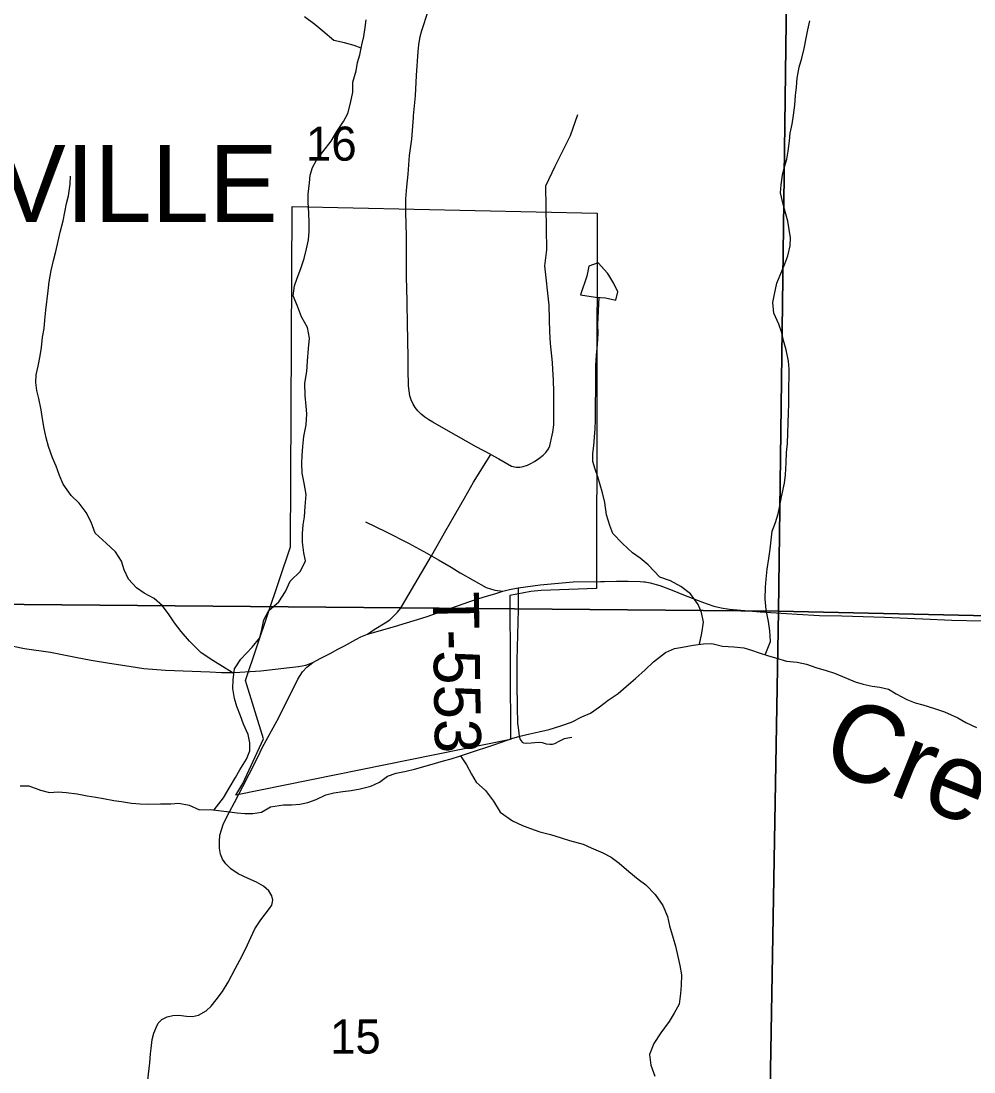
# Model space of a CAD drawing. Extents: x 0 to 34, y 0 to 22.
# Drawn here: x 24.083 to 25.254, y 17.051 to 18.342 of the extents above; entities that cross this region are included whole.
import ezdxf

# ---------------------------------------------------------------- set-up
doc = ezdxf.new("R2010")
doc.units = 0
for name, color, linetype in [('GM_X_City_Street', 7, 'Continuous'), ('GM_X_Corporation', 7, 'Continuous'), ('GM_X_Corporation_Text', 7, 'Continuous'), ('GM_X_Minor_Lake', 7, 'Continuous'), ('GM_X_Minor_River', 7, 'Continuous'), ('GM_X_Minor_River_Text', 7, 'Continuous'), ('GM_X_Section_Text', 7, 'Continuous'), ('GM_X_State_Route', 7, 'Continuous'), ('GM_X_Township_Road', 7, 'Continuous'), ('GM_X_Township_Road_Text', 7, 'Continuous')]:
    doc.layers.add(name, color=color, linetype=linetype)

msp = doc.modelspace()

# ---------------------------------------------------------------- linework, layer by layer
at = {"layer": 'GM_X_City_Street'}
for points in [[(24.5061, 17.7266), (24.5315, 17.7141), (24.559, 17.7002), (24.5815, 17.6882), (24.5875, 17.6847), (24.5961, 17.6798)], [(24.5961, 17.6798), (24.6116, 17.671), (24.6226, 17.6641), (24.6545, 17.646), (24.6651, 17.6427), (24.6751, 17.6415)]]:
    msp.add_lwpolyline(points, dxfattribs=at)
at = {"layer": 'GM_X_Corporation'}
for points in [[(24.0091, 18.6407), (25.0268, 18.6245), (25.0136, 17.617), (23.994, 17.626)], [(25.0268, 18.6245), (26.0385, 18.6067), (26.0272, 17.5944), (25.0136, 17.617)], [(24.3471, 17.3906), (24.3555, 17.4051), (24.3811, 17.4601), (24.3588, 17.5318), (24.4142, 17.696), (24.416, 18.114), (24.7909, 18.106), (24.7901, 17.6448), (24.7223, 17.6424), (24.7096, 17.641), (24.6835, 17.6361), (24.6843, 17.4591)], [(25.0136, 17.617), (24.9957, 16.5834), (23.9803, 16.5962), (23.994, 17.626)], [(26.0272, 17.5944), (26.0142, 16.5672), (24.9957, 16.5834), (25.0136, 17.617)]]:
    msp.add_lwpolyline(points, close=True, dxfattribs=at)
at = {"layer": 'GM_X_Minor_Lake'}
for points in [[(24.8051, 18.0295), (24.8035, 18.032), (24.7921, 18.0449), (24.7807, 18.0407), (24.7781, 18.0285), (24.7704, 18.0054)], [(24.7704, 18.0054), (24.7888, 18.0028), (24.8013, 18.002), (24.8138, 17.999), (24.8165, 18.0093), (24.8115, 18.0195), (24.8051, 18.0295)]]:
    msp.add_lwpolyline(points, dxfattribs=at)
at = {"layer": 'GM_X_Minor_River'}
for points in [[(24.3202, 17.3727), (24.3318, 17.3874), (24.3386, 17.3992), (24.3465, 17.4125), (24.3518, 17.422), (24.3601, 17.435), (24.3643, 17.4452), (24.3643, 17.4551), (24.3623, 17.4653), (24.3566, 17.4778), (24.3528, 17.4881), (24.3482, 17.4998), (24.3452, 17.5097), (24.3432, 17.5218), (24.3436, 17.5325), (24.3455, 17.5458), (24.353, 17.5579), (24.367, 17.5724), (24.3765, 17.5842), (24.3791, 17.5941), (24.3814, 17.6062), (24.3874, 17.6176), (24.3999, 17.6283), (24.4082, 17.6409), (24.4139, 17.6538), (24.4264, 17.666), (24.4324, 17.6785), (24.4305, 17.6884), (24.429, 17.7017), (24.4289, 17.7123), (24.4297, 17.7229), (24.4312, 17.7328), (24.4323, 17.7454), (24.4334, 17.7602), (24.4311, 17.7742), (24.4284, 17.7863), (24.428, 17.7981), (24.4283, 17.808), (24.4291, 17.819), (24.4306, 17.8315), (24.4332, 17.8456), (24.4343, 17.8593), (24.4335, 17.8688), (24.432, 17.8817), (24.4319, 17.8968), (24.4342, 17.9113), (24.4349, 17.9238), (24.4364, 17.9394), (24.4375, 17.9523), (24.4352, 17.9652), (24.4276, 17.9785), (24.4226, 17.9914), (24.4173, 18.0043), (24.4191, 18.0164), (24.4225, 18.0259), (24.427, 18.0377), (24.4308, 18.0502), (24.4338, 18.062), (24.4361, 18.073), (24.4372, 18.0833), (24.4372, 18.0939), (24.4368, 18.1061), (24.436, 18.119), (24.4359, 18.1292), (24.4374, 18.1429), (24.4385, 18.1524), (24.4412, 18.1619), (24.4465, 18.1718), (24.454, 18.1813), (24.4642, 18.1943), (24.471, 18.2061), (24.4794, 18.2186), (24.4847, 18.2281), (24.4877, 18.241), (24.4907, 18.2543), (24.4906, 18.2669), (24.4948, 18.2809), (24.4966, 18.2908), (24.4993, 18.3003), (24.5019, 18.3125), (24.5042, 18.3227), (24.506, 18.3338), (24.5071, 18.3433)], [(24.501, 18.3085), (24.4924, 18.3117), (24.4803, 18.3151), (24.4674, 18.3181), (24.4537, 18.3294), (24.4442, 18.3377), (24.4312, 18.3472)], [(24.9972, 17.5633), (25.0038, 17.5797), (25.0033, 17.5926), (25.0014, 17.604), (24.9984, 17.6184), (24.9972, 17.6321), (24.9979, 17.6465), (24.9986, 17.656), (24.9998, 17.6686), (25.002, 17.6815), (25.0035, 17.6929), (25.0046, 17.7039), (25.0061, 17.7153), (25.0099, 17.7259), (25.0133, 17.7366), (25.0155, 17.7464), (25.0174, 17.7575), (25.0211, 17.7742), (25.0223, 17.7844), (25.023, 17.7989), (25.0237, 17.8118), (25.0248, 17.8228), (25.0252, 17.8357), (25.0255, 17.8478), (25.0259, 17.8604), (25.0266, 17.871), (25.0266, 17.8938), (25.0269, 17.9037), (25.0269, 17.9143), (25.0261, 17.9238), (25.023, 17.9378), (25.02, 17.9492), (25.0177, 17.9587), (25.0142, 17.9693), (25.0081, 17.9829), (25.0066, 17.9959), (25.0088, 18.0065), (25.0119, 18.0198), (25.0156, 18.0297), (25.0217, 18.0437), (25.0251, 18.0532), (25.0281, 18.0658), (25.0284, 18.0757), (25.0269, 18.0859), (25.0253, 18.0958), (25.0211, 18.1106), (25.0188, 18.1201), (25.0161, 18.1307), (25.0169, 18.1406), (25.0188, 18.1527), (25.021, 18.1626), (25.024, 18.1721), (25.0255, 18.182), (25.0274, 18.1945), (25.0281, 18.204), (25.0304, 18.215), (25.0322, 18.2264), (25.0337, 18.2386), (25.0348, 18.2504), (25.0359, 18.2606), (25.0367, 18.2716), (25.0393, 18.2853), (25.0423, 18.2963), (25.0453, 18.3081), (25.0479, 18.321), (25.0498, 18.3309), (25.0521, 18.3423)], [(24.3447, 17.5402), (24.3337, 17.5469), (24.3189, 17.5563), (24.3044, 17.5658), (24.29, 17.5798), (24.2797, 17.5919), (24.2717, 17.6025), (24.2649, 17.6123), (24.2569, 17.6233), (24.2466, 17.6324), (24.2344, 17.6388), (24.2249, 17.6456), (24.215, 17.6562), (24.2097, 17.6676), (24.2063, 17.6782), (24.199, 17.6899), (24.1876, 17.7005), (24.1743, 17.7126), (24.1693, 17.7263), (24.1629, 17.738), (24.1545, 17.7494), (24.1446, 17.7589), (24.1347, 17.7729), (24.1305, 17.7835), (24.1263, 17.7949), (24.1217, 17.8051), (24.1168, 17.8191), (24.1141, 17.8298), (24.1114, 17.8412), (24.1095, 17.8533), (24.1076, 17.8643), (24.1049, 17.8783), (24.1026, 17.8878), (24.1014, 17.8977), (24.1018, 17.9072), (24.104, 17.9178), (24.1066, 17.9304), (24.1081, 17.9406), (24.1096, 17.9535), (24.1115, 17.9642), (24.1122, 17.9744), (24.1137, 17.9866), (24.1163, 18.0105), (24.1178, 18.0215), (24.1201, 18.0352), (24.1231, 18.0477), (24.1257, 18.0588), (24.1287, 18.0713), (24.1313, 18.0823), (24.1347, 18.0964), (24.137, 18.107), (24.1388, 18.1177), (24.1415, 18.1272), (24.1433, 18.1416), (24.1437, 18.1511)], [(24.9168, 17.5761), (24.9195, 17.5897), (24.9214, 17.6034), (24.9191, 17.6152), (24.9149, 17.625), (24.9057, 17.6383), (24.8939, 17.647), (24.881, 17.6541), (24.8681, 17.6587), (24.8537, 17.6738), (24.8438, 17.6821), (24.8343, 17.6885), (24.8221, 17.6999), (24.8103, 17.7124), (24.8065, 17.7222), (24.8023, 17.7351), (24.8004, 17.7503), (24.7977, 17.7621), (24.7916, 17.7818), (24.7885, 17.7913), (24.7858, 17.8008), (24.7858, 17.8106), (24.7869, 17.8201), (24.7876, 17.8308), (24.7884, 17.841), (24.7887, 17.8513), (24.7891, 17.8638), (24.7891, 17.8737), (24.7894, 17.8862), (24.7893, 17.9185), (24.7901, 17.9314), (24.7912, 17.9443), (24.7923, 17.958), (24.7919, 17.969), (24.7936, 18.0025)], [(24.8168, 17.5157), (24.8267, 17.5241), (24.838, 17.534), (24.8501, 17.5447), (24.86, 17.5546), (24.8751, 17.566), (24.8861, 17.571), (24.896, 17.5726), (24.9089, 17.5749), (24.9214, 17.5768), (24.9317, 17.5772), (24.9449, 17.5739), (24.959, 17.5728), (24.9711, 17.5717), (24.9806, 17.569), (24.9901, 17.5656), (25.0004, 17.5623), (25.0102, 17.5593), (25.0235, 17.5555), (25.0368, 17.554), (25.0482, 17.5518), (25.0596, 17.5476), (25.0725, 17.5439), (25.0824, 17.5405), (25.0972, 17.5345), (25.1078, 17.53), (25.1177, 17.5273), (25.1287, 17.5247), (25.1382, 17.5236), (25.1488, 17.521), (25.1583, 17.5153), (25.1716, 17.5081), (25.1815, 17.504), (25.191, 17.5017), (25.2054, 17.4972), (25.2176, 17.4931), (25.2339, 17.4859), (25.2438, 17.4799), (25.2571, 17.4739)], [(24.082, 17.4022), (24.0927, 17.4022), (24.1071, 17.3969), (24.1181, 17.3939), (24.1287, 17.3947), (24.1386, 17.394), (24.1519, 17.3922), (24.1644, 17.3899), (24.175, 17.3881), (24.1845, 17.3866), (24.1971, 17.3843), (24.2066, 17.3828), (24.2187, 17.381), (24.2293, 17.3803), (24.2392, 17.3799), (24.2544, 17.38), (24.2673, 17.38), (24.2768, 17.3808), (24.2897, 17.3785), (24.3022, 17.3729), (24.3155, 17.3733), (24.3288, 17.3715), (24.339, 17.3704), (24.3485, 17.3689), (24.358, 17.3681), (24.3679, 17.3682), (24.3785, 17.3697), (24.3895, 17.3766), (24.4054, 17.3789), (24.4153, 17.3789), (24.4255, 17.3797), (24.4354, 17.3817), (24.4456, 17.3855), (24.4574, 17.3912), (24.4672, 17.3935), (24.4786, 17.3951), (24.4885, 17.3966), (24.4999, 17.3986), (24.5127, 17.402), (24.5234, 17.4066), (24.5332, 17.4139), (24.5438, 17.4177), (24.5563, 17.4204), (24.5666, 17.4227), (24.5795, 17.4262), (24.5924, 17.43), (24.6022, 17.4331), (24.6117, 17.4354), (24.6219, 17.4388), (24.6341, 17.4427), (24.6439, 17.4461), (24.6542, 17.4492), (24.664, 17.4526), (24.6735, 17.4557), (24.686, 17.4603), (24.6959, 17.4634), (24.7084, 17.4661), (24.7194, 17.4684), (24.7319, 17.4714), (24.7463, 17.476), (24.7596, 17.4806), (24.7721, 17.4868), (24.7827, 17.4913), (24.7937, 17.4994), (24.8043, 17.5074), (24.8168, 17.5157)], [(24.623, 17.4392), (24.6303, 17.4282), (24.6364, 17.4165), (24.6421, 17.4066), (24.6539, 17.3964), (24.6634, 17.3835), (24.6718, 17.3699), (24.687, 17.3593), (24.6992, 17.3533), (24.709, 17.3499), (24.7204, 17.3458), (24.7337, 17.3424), (24.7466, 17.3382), (24.7569, 17.3352), (24.7736, 17.3304), (24.7835, 17.3262), (24.7979, 17.3198), (24.8082, 17.3145), (24.818, 17.3073), (24.8298, 17.2968), (24.8412, 17.2877), (24.8507, 17.2805), (24.8622, 17.2688), (24.8717, 17.2551), (24.8774, 17.2415), (24.8797, 17.2301), (24.8843, 17.2149), (24.887, 17.2054), (24.89, 17.1926), (24.8927, 17.1816), (24.8946, 17.1702), (24.8943, 17.1569), (24.8932, 17.147), (24.8917, 17.1341), (24.8856, 17.1231), (24.8796, 17.1128), (24.869, 17.0987), (24.8607, 17.0858), (24.8554, 17.0721), (24.8569, 17.0592), (24.8619, 17.0456)]]:
    msp.add_lwpolyline(points, dxfattribs=at)
at = {"layer": 'GM_X_State_Route'}
for points in [[(24.5652, 18.2232), (24.5654, 18.2253), (24.5677, 18.2498), (24.5689, 18.275), (24.5711, 18.3043), (24.572, 18.3125), (24.5736, 18.3227), (24.5755, 18.3301), (24.5834, 18.354)], [(24.5558, 18.1236), (24.5571, 18.1381), (24.5589, 18.1538), (24.5605, 18.1767), (24.5631, 18.1969), (24.5652, 18.2232)], [(24.5088, 17.5884), (24.517, 17.5942), (24.5305, 17.6025), (24.5362, 17.6063), (24.5413, 17.6109), (24.5456, 17.6154), (24.5491, 17.6201), (24.5518, 17.624), (24.5752, 17.6638), (24.5875, 17.6847), (24.6049, 17.7158), (24.628, 17.7556), (24.6391, 17.7752), (24.6601, 17.8092), (24.6423, 17.8187), (24.6056, 17.8395), (24.5891, 17.849), (24.5842, 17.8517), (24.5794, 17.8552), (24.5749, 17.8588), (24.5708, 17.8629), (24.5672, 17.8672), (24.5647, 17.8712), (24.5623, 17.8765), (24.5607, 17.8813), (24.5592, 17.8938), (24.5588, 17.9139), (24.5588, 17.9286), (24.5581, 17.9707), (24.5575, 17.9946), (24.5569, 18.016), (24.5567, 18.0241), (24.5567, 18.0502), (24.5565, 18.0781), (24.5559, 18.1067), (24.5558, 18.1236)], [(24.5088, 17.5884), (24.5421, 17.598), (24.5809, 17.6099), (24.6344, 17.6287), (24.6457, 17.6322), (24.6551, 17.6352), (24.6653, 17.6382), (24.6751, 17.6415), (24.6833, 17.6433), (24.6939, 17.6456), (24.7208, 17.6493), (24.7613, 17.6529), (24.7951, 17.6531), (24.7999, 17.6532)], [(24.7999, 17.6532), (24.8145, 17.6536), (24.8291, 17.6537), (24.8438, 17.6533), (24.8482, 17.6529)], [(24.8482, 17.6529), (24.85, 17.6527), (24.8561, 17.6517), (24.8679, 17.6483), (24.8833, 17.6428), (24.8971, 17.637), (24.9202, 17.6277), (24.9343, 17.6228), (24.9434, 17.6209), (24.9536, 17.6194), (24.9912, 17.6162), (25.0368, 17.613), (25.0641, 17.6116), (25.0914, 17.6111), (25.1438, 17.6096), (25.1911, 17.6072), (25.2266, 17.6056), (25.263, 17.6051)], [(24.4414, 17.5536), (24.4516, 17.559), (24.4628, 17.5649), (24.4724, 17.5701), (24.4803, 17.5743), (24.4946, 17.5822), (24.5007, 17.5853), (24.5088, 17.5884)], [(24.0411, 17.5803), (24.0875, 17.5711), (24.1192, 17.5663), (24.1501, 17.5605), (24.1692, 17.5567), (24.1916, 17.5528), (24.2106, 17.5502), (24.2341, 17.5465), (24.2607, 17.5445), (24.3149, 17.5421), (24.3293, 17.5413), (24.344, 17.5414), (24.3519, 17.5418), (24.3647, 17.5427)], [(24.3768, 17.4435), (24.3799, 17.4497), (24.3972, 17.4817), (24.4157, 17.518), (24.4232, 17.5332), (24.429, 17.5421), (24.4344, 17.5479), (24.4414, 17.5536)], [(24.413, 17.5475), (24.4241, 17.5488), (24.4329, 17.5503), (24.4414, 17.5536)], [(24.3647, 17.5427), (24.3776, 17.5436), (24.413, 17.5475)], [(24.3453, 17.3818), (24.3554, 17.4015), (24.3711, 17.4318), (24.3768, 17.4435)], [(24.2378, 17.0302), (24.2412, 17.0618), (24.2423, 17.0731), (24.2428, 17.0797), (24.2443, 17.0906), (24.2461, 17.0983), (24.2493, 17.1063), (24.2515, 17.1105), (24.2559, 17.1151), (24.2625, 17.1183), (24.2695, 17.1199), (24.2771, 17.1206), (24.2863, 17.1193), (24.2936, 17.1188), (24.3013, 17.1204), (24.3106, 17.1256), (24.3166, 17.1317), (24.3227, 17.1392), (24.3304, 17.1497), (24.3377, 17.1612), (24.3463, 17.1773), (24.3549, 17.1935), (24.3615, 17.2069), (24.3654, 17.216), (24.3704, 17.2265), (24.3777, 17.2376), (24.3883, 17.2514), (24.3911, 17.2557), (24.3926, 17.2616), (24.3911, 17.2669), (24.3874, 17.2734), (24.3808, 17.2789), (24.3724, 17.2837), (24.3622, 17.2884), (24.3499, 17.2943), (24.3409, 17.3002), (24.3347, 17.3062), (24.3304, 17.312), (24.3282, 17.3184), (24.327, 17.3257), (24.3268, 17.3339), (24.3275, 17.3418), (24.3293, 17.348), (24.332, 17.3559), (24.3393, 17.3702), (24.3453, 17.3818)]]:
    msp.add_lwpolyline(points, dxfattribs=at)
at = {"layer": 'GM_X_Township_Road'}
for points in [[(24.6601, 17.8092), (24.6702, 17.804), (24.6857, 17.7951), (24.6915, 17.7939), (24.696, 17.7936), (24.7, 17.7946), (24.7052, 17.7962), (24.7094, 17.7981), (24.7139, 17.8009), (24.7192, 17.8043), (24.7247, 17.8084), (24.7278, 17.8116), (24.731, 17.8163), (24.7328, 17.8201), (24.7336, 17.8236), (24.735, 17.8295), (24.7364, 17.8366), (24.7376, 17.8457), (24.7379, 17.8571), (24.7377, 17.8729), (24.7377, 17.8861), (24.7371, 17.9012), (24.7364, 17.9136), (24.7359, 17.9225), (24.7338, 17.9458), (24.7327, 17.9599), (24.7325, 17.975), (24.732, 17.9927), (24.7265, 18.0411), (24.7289, 18.0609), (24.7278, 18.1394), (24.7392, 18.1637), (24.7583, 18.2012), (24.7673, 18.2269)], [(24.6939, 17.6456), (24.6938, 17.6357), (24.694, 17.6187), (24.6929, 17.5877), (24.6922, 17.5566), (24.6922, 17.5281), (24.6926, 17.4988), (24.6932, 17.4793), (24.6941, 17.4708), (24.6952, 17.4632), (24.6965, 17.4593), (24.6986, 17.4558), (24.7005, 17.455), (24.7042, 17.4546), (24.7098, 17.455), (24.7142, 17.4556), (24.7196, 17.456), (24.7235, 17.4555), (24.7281, 17.454), (24.7327, 17.4533), (24.7359, 17.4533), (24.7389, 17.4542), (24.745, 17.4574), (24.7508, 17.4604), (24.7548, 17.4613), (24.76, 17.462)]]:
    msp.add_lwpolyline(points, dxfattribs=at)

# ---------------------------------------------------------------- texts
at = {"layer": 'GM_X_Corporation_Text'}
msp.add_text('BATESVILLE', height=0.0947, rotation=0, dxfattribs=at).set_placement((23.6383, 18.0949))
at = {"layer": 'GM_X_Minor_River_Text'}
msp.add_text('Creek', height=0.0947, rotation=338.1293, dxfattribs=at).set_placement((25.0621, 17.4275))
at = {"layer": 'GM_X_Section_Text'}
for s, p in [('16', (24.4332, 18.1703)), ('15', (24.4628, 17.0733))]:
    msp.add_text(s, height=0.04186, rotation=0, dxfattribs=at).set_placement(p)
at = {"layer": 'GM_X_Township_Road_Text'}
msp.add_text('T-553', height=0.05682, rotation=270.8421, dxfattribs=at).set_placement((24.5888, 17.6404))

doc.saveas('drawing.dxf')
